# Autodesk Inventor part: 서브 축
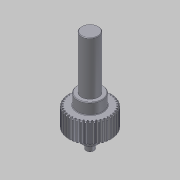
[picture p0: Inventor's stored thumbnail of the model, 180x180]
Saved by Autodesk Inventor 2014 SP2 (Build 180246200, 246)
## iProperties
Created: 2014-07
Part Number: 서브 축
Material: 강
Document SubType Name: Modeling
Designer: KYOUNG IL JANG
Categories: <?xml version="1.0" encoding="UTF-16"?> <MemberInstance><Categories><FamilyTemplate><FamilyTemplateParameter ValueType="xs:double" Id="1" ObjectReferenceKey="da
Density: 1 g/cm^3
Appearance: 강철
CustomPartVersion: 1
Company: 한국ATC센터
Author: KYOUNG IL JANG
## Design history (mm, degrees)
sketch "Sketch1"
  geometry: C1 r 21 at (0, 0)
  constraints: 1 centre point
  dimensions: "d0" = 42 diameter of C1 (= da_da)
extrude "Extrusion1" new body sketch "Sketch1" distance "d1" = 20 (= da_b); taper "d2" = 0 deg
workplane "Work Plane2"
feature "피치 지름" dims "d4" = 10, "d5" = 0
workplane "Work Plane8"
workplane "Work Plane9"
chamfer "모따기1" distance "d49" = 1; stored, may be unused: second distance "d50" = 2, angle "d51" = 45 deg
sketch "스케치3"
  geometry: C1 r 12.5 at (0, 0); 1 further point
  constraints: 1 centre point, 1 coincident
  dimensions: "d52" = 25 diameter of C1
extrude "돌출2" join sketch "스케치3" distance "d53" = 11; taper "d54" = 0 deg
sketch "스케치4"
  geometry: C1 r 8.5 at (0, 0); 1 further point
  constraints: 1 centre point, 1 coincident
  dimensions: "d55" = 17 diameter of C1
extrude "돌출3" join sketch "스케치4" distance "d56" = 53; taper "d57" = 0 deg
sketch "스케치5"
  geometry: C1 r 7.5 at (0, 0); 1 further point
  constraints: 1 centre point, 1 coincident
  dimensions: "d62" = 15 diameter of C1
extrude "돌출4" join sketch "스케치5" distance "d63" = 11; taper "d64" = 0 deg
sketch "스케치6"
  geometry: C1 r 4 at (0, 0); 1 further point
  constraints: 1 centre point, 1 coincident
  dimensions: "d65" = 8 diameter of C1
extrude "돌출5" join sketch "스케치6" distance "d66" = 7; taper "d67" = 0 deg
chamfer "모따기2" distance "d58" = 0.5; stored, may be unused: second distance "d59" = 2, angle "d60" = 45 deg
fillet "모깎기1" dims "d61" = 0.5
feature "스퍼 기어" dims "da_b" = 20, "da_d" = 40, "da_aw" = 31, "da_da" = 42, "da_df" = 37.5, "da_dw" = 40, angle "da_beta" = 0 deg, "da_lefttooth" = 0, "da_righttooth" = 0
body "Solid1"
sketch "Sketch2"
  geometry: C1 r 21 at (0, 0) reference; C2 r 20 at (0, 0)
  constraints: 1 centre point, 1 coincident
  dimensions: "d3" = 40 diameter of C2 (= da_dw)
body "Srf1"
other parameters: "d16" = 31 (= da_aw), "d17" = 0, "d34" = 4.5 deg (computed from da_z), "d39" = 0, "d41" = 0, "d43" = 31 (= da_aw), "d46" = 31 (= da_aw), "d47" = 0, "d48" = 0
